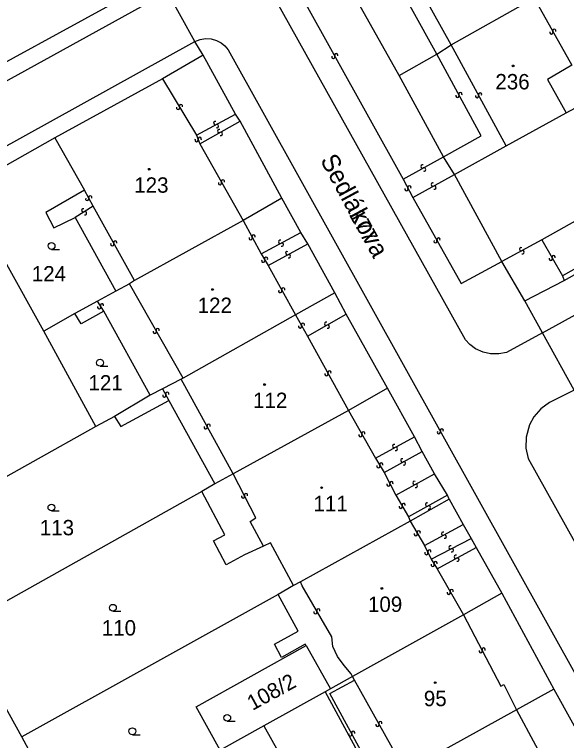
# Model space of a CAD drawing. Extents: x -600391 to -599491, y -1160176 to -1159402.
# Drawn here: x -600288.8 to -600227.7, y -1159912.4 to -1159832 of the extents above; entities that cross this region are included whole.
import ezdxf

# ---------------------------------------------------------------- set-up
doc = ezdxf.new("R2010")
doc.units = 0
for name, color, linetype in [('Level 1', 7, 'Continuous'), ('Level 11', 7, 'Continuous'), ('Level 13', 7, 'Continuous'), ('Level 3', 7, 'Continuous'), ('Level 4', 7, 'Continuous'), ('Level 5', 7, 'Continuous')]:
    doc.layers.add(name, color=color, linetype=linetype)

msp = doc.modelspace()

# ---------------------------------------------------------------- linework, layer by layer
at = {"layer": 'Level 1'}
for points in [[(-600246.18, -1159838.78), (-600254.51, -1159823.88)], [(-600272.73, -1159827.94), (-600300.01, -1159842.88)], [(-600268.81, -1159835), (-600271.82, -1159829.5)], [(-600240.43, -1159835.36), (-600231.24, -1159830.17)], [(-600267.88, -1159836.52), (-600268.81, -1159835)], [(-600242.02, -1159836.39), (-600240.43, -1159835.36)], [(-600267.88, -1159836.52), (-600272.39, -1159839.13)], [(-600264.3, -1159843.04), (-600267.88, -1159836.52)], [(-600246.18, -1159838.78), (-600242.02, -1159836.39)], [(-600227.68, -1159842.88), (-600223.47, -1159840.63), (-600223.45, -1159840.03), (-600223.3, -1159839.51), (-600223.07, -1159839.09), (-600222.75, -1159838.72), (-600222.28, -1159838.38), (-600221.8, -1159838.18), (-600221.24, -1159838.09), (-600220.7, -1159838.14), (-600220.19, -1159838.3), (-600219.88, -1159838.48), (-600215.56, -1159836.16)], [(-600241.28, -1159847.75), (-600246.18, -1159838.78)], [(-600272.39, -1159839.13), (-600284.31, -1159845.68)], [(-600234.32, -1159846.54), (-600227.68, -1159842.88)], [(-600263.79, -1159843.81), (-600264.3, -1159843.04)], [(-600259.17, -1159852.34), (-600263.79, -1159843.81)], [(-600284.31, -1159845.68), (-600294.32, -1159851.32)], [(-600284.31, -1159845.68), (-600281.03, -1159851.47)], [(-600240.07, -1159849.73), (-600234.32, -1159846.54)], [(-600240.07, -1159849.73), (-600241.28, -1159847.75)], [(-600234.8, -1159859.37), (-600240.07, -1159849.73)], [(-600227.9, -1159861.47), (-600208.01, -1159850.29)], [(-600285.53, -1159867.08), (-600294.32, -1159851.32)], [(-600281.03, -1159851.47), (-600285.31, -1159853.92), (-600284.4, -1159855.61), (-600282.05, -1159854.47)], [(-600259.17, -1159852.34), (-600263.45, -1159854.82)], [(-600257.06, -1159856.13), (-600259.17, -1159852.34)], [(-600282.05, -1159854.47), (-600277.54, -1159862.64)], [(-600263.45, -1159854.82), (-600275.49, -1159861.45)], [(-600256.28, -1159857.41), (-600257.06, -1159856.13)], [(-600253.31, -1159862.81), (-600256.28, -1159857.41)], [(-600232.25, -1159863.72), (-600234.8, -1159859.37)], [(-600275.49, -1159861.45), (-600276.04, -1159861.83)], [(-600232.25, -1159863.72), (-600227.9, -1159861.47)], [(-600276.04, -1159861.83), (-600277.54, -1159862.64)], [(-600277.54, -1159862.64), (-600279.58, -1159863.74)], [(-600253.31, -1159862.81), (-600257.67, -1159865.27)], [(-600252.05, -1159865.19), (-600253.31, -1159862.81)], [(-600279.58, -1159863.74), (-600282.08, -1159865.09)], [(-600230.31, -1159867.23), (-600232.25, -1159863.72)], [(-600282.08, -1159865.09), (-600285.53, -1159867.08)], [(-600278.88, -1159864.85), (-600281.38, -1159866.25), (-600282.08, -1159865.09)], [(-600273.74, -1159874.15), (-600278.88, -1159864.85)], [(-600257.67, -1159865.27), (-600270.1, -1159872.26)], [(-600247.47, -1159873.37), (-600252.05, -1159865.19)], [(-600279.76, -1159877.63), (-600285.53, -1159867.08)], [(-600226.79, -1159873.6), (-600230.31, -1159867.23)], [(-600270.32, -1159872.39), (-600272.38, -1159873.45)], [(-600270.1, -1159872.26), (-600270.32, -1159872.39)], [(-600272.38, -1159873.45), (-600273.74, -1159874.15)], [(-600247.47, -1159873.37), (-600251.8, -1159875.84)], [(-600244.49, -1159878.77), (-600247.47, -1159873.37)], [(-600273.74, -1159874.15), (-600277.69, -1159876.51)], [(-600277.69, -1159876.51), (-600276.98, -1159877.6), (-600271.67, -1159874.72)], [(-600271.67, -1159874.72), (-600266.6, -1159883.96)], [(-600251.8, -1159875.84), (-600264.54, -1159882.86)], [(-600277.69, -1159876.51), (-600279.76, -1159877.63)], [(-600279.76, -1159877.63), (-600300.73, -1159889.34)], [(-600243.65, -1159880.38), (-600244.49, -1159878.77)], [(-600242.27, -1159882.85), (-600243.65, -1159880.38)], [(-600264.54, -1159882.86), (-600266.6, -1159883.96)], [(-600240.84, -1159885.23), (-600242.27, -1159882.85)], [(-600266.6, -1159883.96), (-600268.03, -1159884.8)], [(-600268.03, -1159884.8), (-600294.72, -1159899.77)], [(-600261.19, -1159890.85), (-600263.31, -1159891.81), (-600265.35, -1159892.93), (-600266.73, -1159890.28), (-600265.49, -1159889.6), (-600268.03, -1159884.8)], [(-600240.66, -1159885.66), (-600240.84, -1159885.23)], [(-600240.66, -1159885.66), (-600244.97, -1159888.08)], [(-600240.66, -1159885.66), (-600239.08, -1159888.47)], [(-600244.97, -1159888.08), (-600257.12, -1159894.82)], [(-600239.08, -1159888.47), (-600238.21, -1159890.03)], [(-600238.21, -1159890.03), (-600237.66, -1159891.01)], [(-600257.87, -1159895.23), (-600260.44, -1159890.48), (-600261.19, -1159890.85)], [(-600237.66, -1159891.01), (-600234.81, -1159896.08)], [(-600257.12, -1159894.82), (-600257.87, -1159895.23)], [(-600257.87, -1159895.23), (-600259.59, -1159896.22)], [(-600259.59, -1159896.22), (-600287.96, -1159911.98)], [(-600256.49, -1159901.87), (-600256.58, -1159901.71), (-600259.19, -1159903.19), (-600259.97, -1159901.72), (-600257.35, -1159900.26), (-600259.59, -1159896.22)], [(-600234.81, -1159896.08), (-600239.07, -1159898.45)], [(-600234.81, -1159896.08), (-600229.06, -1159906.7)], [(-600239.07, -1159898.45), (-600251.33, -1159905.28)], [(-600287.96, -1159911.98), (-600293.45, -1159902.08)], [(-600265.99, -1159913.45), (-600268.66, -1159908.65), (-600256.49, -1159901.87)], [(-600256.49, -1159901.87), (-600253.78, -1159906.65)], [(-600251.33, -1159905.28), (-600253.78, -1159906.65)], [(-600254.37, -1159906.98), (-600261.15, -1159910.76)], [(-600253.78, -1159906.65), (-600254.37, -1159906.98)], [(-600254.37, -1159906.98), (-600249.34, -1159916.24)], [(-600229.06, -1159906.7), (-600233.2, -1159908.96)], [(-600229.06, -1159906.7), (-600224.75, -1159914.47)], [(-600233.2, -1159908.96), (-600244.6, -1159915.29)], [(-600261.15, -1159910.76), (-600265.99, -1159913.45)], [(-600261.15, -1159910.76), (-600255.53, -1159920.84)], [(-600285.41, -1159916.7), (-600287.96, -1159911.98)]]:
    msp.add_lwpolyline(points, dxfattribs=at)
at = {"layer": 'Level 13'}
for centre, start, end in [((-600229.321, -1159833.989), 156.39539, 28.98539), ((-600228.998, -1159833.811), 336.60985, 208.70785), ((-600253.148, -1159836.512), 336.3917, 208.4897), ((-600253.471, -1159836.689), 156.17724, 28.76724), ((-600239.723, -1159841.006), 155.8544, 27.9524), ((-600239.398, -1159840.833), 335.63994, 208.22994), ((-600237.543, -1159841.037), 156.02985, 28.12785), ((-600237.218, -1159840.862), 335.81539, 208.40539), ((-600270.342, -1159842.156), 338.68684, 210.78483), ((-600270.658, -1159842.345), 158.47238, 31.06238), ((-600266.536, -1159844.037), 65.72114, 297.81914), ((-600266.363, -1159844.362), 245.50669, 118.09669), ((-600266.109, -1159844.908), 66.78523, 298.88323), ((-600265.93, -1159845.231), 246.57077, 119.16077), ((-600268.604, -1159845.91), 146.47463, 19.06463), ((-600268.255, -1159845.791), 326.68909, 198.78708), ((-600243.599, -1159848.838), 66.64503, 298.74302), ((-600243.421, -1159849.161), 246.43057, 119.02057), ((-600266.021, -1159850.67), 156.69195, 29.28195), ((-600265.699, -1159850.491), 336.90641, 209.00441), ((-600245.046, -1159851.165), 335.40082, 207.49881), ((-600242.457, -1159850.838), 66.18353, 298.28153), ((-600242.282, -1159851.162), 245.96907, 118.55907), ((-600245.373, -1159851.336), 155.18636, 27.77636), ((-600280.713, -1159852.427), 156.12065, 28.21864), ((-600280.388, -1159852.252), 335.90619, 208.49619), ((-600281.158, -1159853.684), 69.42303, 302.01303), ((-600280.963, -1159853.997), 249.63749, 121.73549), ((-600262.297, -1159856.584), 335.52553, 207.62353), ((-600277.942, -1159857.428), 156.4687, 28.56669), ((-600277.619, -1159857.251), 336.25424, 208.84424), ((-600262.623, -1159856.756), 155.31108, 27.90108), ((-600259.346, -1159857.167), 65.82822, 297.92621), ((-600259.173, -1159857.492), 245.61376, 118.20376), ((-600242.151, -1159857.11), 156.51318, 29.10318), ((-600241.828, -1159856.931), 336.72763, 208.82563), ((-600258.566, -1159858.437), 65.78209, 297.88009), ((-600232.688, -1159857.998), 65.81423, 298.40423), ((-600232.513, -1159858.323), 246.02869, 118.12668), ((-600260.912, -1159859.064), 339.2563, 211.35429), ((-600258.393, -1159858.762), 245.56764, 118.15764), ((-600229.4, -1159859.051), 157.11919, 29.70919), ((-600229.079, -1159858.869), 337.33365, 209.43165), ((-600261.227, -1159859.257), 159.04184, 31.63184), ((-600259.018, -1159862.443), 336.15141, 208.24941), ((-600259.342, -1159862.618), 155.93695, 28.52695), ((-600279.387, -1159864.397), 159.60952, 31.70752), ((-600279.074, -1159864.203), 339.39506, 211.98506), ((-600256.83, -1159866.349), 337.4317, 209.5297), ((-600254.27, -1159866.239), 67.07414, 299.17214), ((-600273.231, -1159867.13), 157.03472, 29.13272), ((-600272.91, -1159866.95), 336.82027, 209.41027), ((-600257.15, -1159866.531), 157.21725, 29.80725), ((-600254.09, -1159866.56), 246.85969, 119.44969), ((-600254.222, -1159871.818), 155.91017, 28.50017), ((-600253.897, -1159871.643), 336.12463, 208.22263), ((-600272.181, -1159874.169), 156.36588, 28.95588), ((-600271.858, -1159873.991), 336.58033, 208.67833), ((-600267.268, -1159877.532), 336.05933, 208.64933), ((-600267.592, -1159877.708), 156.27378, 28.37178), ((-600250.139, -1159878.39), 337.05915, 209.15715), ((-600241.781, -1159878.229), 156.24801, 28.83801), ((-600241.458, -1159878.052), 336.46246, 208.56046), ((-600250.46, -1159878.57), 156.84469, 29.43469), ((-600246.727, -1159879.777), 66.02985, 298.12785), ((-600246.552, -1159880.102), 245.81539, 118.40539), ((-600245.828, -1159881.378), 66.45055, 298.54855), ((-600245.651, -1159881.701), 246.2361, 118.8261), ((-600248.468, -1159882.014), 158.01593, 30.60593), ((-600248.151, -1159881.827), 338.23039, 210.32838), ((-600247.364, -1159884.044), 154.5457, 27.1357), ((-600247.035, -1159883.877), 334.76016, 206.85815), ((-600244.497, -1159883.858), 66.1424, 298.2404), ((-600244.322, -1159884.182), 245.92794, 118.51794), ((-600263.465, -1159885.372), 154.45522, 26.55322), ((-600263.136, -1159885.207), 334.24076, 206.83076), ((-600245.68, -1159886.308), 337.80697, 209.90497), ((-600243.078, -1159886.258), 66.0202, 298.6102), ((-600245.999, -1159886.493), 157.59251, 30.18251), ((-600242.902, -1159886.582), 246.23465, 118.33265), ((-600244.329, -1159889.533), 157.62382, 30.21382), ((-600244.01, -1159889.348), 337.83828, 209.93628), ((-600241.307, -1159889.477), 65.88016, 297.97816), ((-600241.133, -1159889.802), 245.66571, 118.25571), ((-600240.512, -1159890.995), 64.4015, 296.4995), ((-600240.347, -1159891.324), 244.18704, 116.77704), ((-600243.166, -1159891.62), 153.26003, 25.85003), ((-600242.834, -1159891.46), 333.47449, 205.57248), ((-600239.907, -1159892.037), 66.12239, 298.22039), ((-600242.151, -1159892.746), 338.56783, 210.66583), ((-600239.732, -1159892.362), 245.90794, 118.49794), ((-600242.468, -1159892.935), 158.35337, 30.94338), ((-600240.68, -1159896.011), 157.01257, 29.60257), ((-600240.359, -1159895.83), 337.22703, 209.32503), ((-600255.44, -1159898.172), 157.68629, 29.78429), ((-600255.121, -1159897.988), 337.47183, 210.06183), ((-600237.153, -1159902.485), 154.92878, 27.51878), ((-600236.826, -1159902.316), 335.14323, 207.24123), ((-600248.259, -1159910.451), 336.4035, 208.9935), ((-600248.582, -1159910.629), 156.61796, 28.71595), ((-600251.593, -1159911.697), 155.96511, 28.06311), ((-600251.268, -1159911.523), 335.75065, 208.34065)]:
    msp.add_arc(centre, 0.184, start, end, dxfattribs=at)
at = {"layer": 'Level 3'}
for points in [[(-600230.31, -1159867.23), (-600234.28, -1159869.41), (-600235.16, -1159869.58), (-600236.07, -1159869.58), (-600236.89, -1159869.39), (-600237.73, -1159869.01), (-600238.36, -1159868.54), (-600238.85, -1159868.03), (-600259.85, -1159830.4), (-600267.23, -1159824.89), (-600328.56, -1159715.49), (-600329.16, -1159714.44), (-600329.45, -1159713.11), (-600329.33, -1159711.96), (-600329.03, -1159711.13)], [(-600240.43, -1159835.36), (-600248.6, -1159820.64)], [(-600242.02, -1159836.39), (-600250.24, -1159821.55)], [(-600260.89, -1159822.94), (-600245.74, -1159850.25)], [(-600373.95, -1159885.79), (-600271.82, -1159829.5)], [(-600230.31, -1159867.23), (-600164.72, -1159831.16), (-600163.95, -1159830.52), (-600163.4, -1159829.75)], [(-600231.24, -1159830.17), (-600227.07, -1159837.62), (-600229.77, -1159839.19), (-600227.68, -1159842.88)], [(-600268.81, -1159835), (-600268.21, -1159834.77), (-600267.62, -1159834.68), (-600267.01, -1159834.71), (-600266.39, -1159834.88), (-600265.88, -1159835.15), (-600265.47, -1159835.49), (-600265.11, -1159835.91), (-600218.12, -1159920.37), (-600217.94, -1159920.94), (-600217.91, -1159921.6), (-600218.02, -1159922.19), (-600218.24, -1159922.81), (-600218.57, -1159923.26), (-600218.96, -1159923.67), (-600219.39, -1159923.97)], [(-600369.85, -1159890.97), (-600268.81, -1159835)], [(-600234.32, -1159846.54), (-600240.43, -1159835.36)], [(-600241.28, -1159847.75), (-600237.11, -1159845.44), (-600242.02, -1159836.39)], [(-600272.39, -1159839.13), (-600268.6, -1159845.36)], [(-600268.6, -1159845.36), (-600264.3, -1159843.04)], [(-600268.26, -1159846.33), (-600263.79, -1159843.81)], [(-600268.6, -1159845.36), (-600268.26, -1159846.33)], [(-600210.89, -1159846.04), (-600230.39, -1159856.96)], [(-600210.89, -1159846.04), (-600208.7, -1159850.11), (-600228.09, -1159860.95)], [(-600268.26, -1159846.33), (-600263.45, -1159854.82)], [(-600245.74, -1159850.25), (-600241.28, -1159847.75)], [(-600244.67, -1159852.26), (-600240.07, -1159849.73)], [(-600245.74, -1159850.25), (-600244.67, -1159852.26)], [(-600280.07, -1159853.22), (-600281.03, -1159851.47)], [(-600244.67, -1159852.26), (-600239.31, -1159861.79), (-600234.8, -1159859.37)], [(-600280.07, -1159853.22), (-600282.05, -1159854.47)], [(-600275.49, -1159861.45), (-600280.07, -1159853.22)], [(-600263.45, -1159854.82), (-600261.47, -1159858.52)], [(-600261.47, -1159858.52), (-600257.06, -1159856.13)], [(-600260.68, -1159859.79), (-600256.28, -1159857.41)], [(-600230.39, -1159856.96), (-600234.8, -1159859.37)], [(-600230.39, -1159856.96), (-600228.09, -1159860.95)], [(-600261.47, -1159858.52), (-600260.68, -1159859.79)], [(-600260.68, -1159859.79), (-600257.67, -1159865.27)], [(-600228.09, -1159860.95), (-600227.9, -1159861.47)], [(-600270.1, -1159872.26), (-600276.04, -1159861.83)], [(-600278.88, -1159864.85), (-600279.58, -1159863.74)], [(-600257.67, -1159865.27), (-600256.31, -1159867.62)], [(-600256.31, -1159867.62), (-600252.05, -1159865.19)], [(-600256.31, -1159867.62), (-600251.8, -1159875.84)], [(-600264.54, -1159882.86), (-600270.32, -1159872.39)], [(-600272.38, -1159873.45), (-600271.67, -1159874.72)], [(-600226.79, -1159873.6), (-600229.16, -1159874.79), (-600229.52, -1159874.97), (-600230.51, -1159875.67), (-600231.28, -1159876.56), (-600231.76, -1159877.43), (-600232.13, -1159878.78), (-600232.17, -1159880), (-600231.89, -1159881.14), (-600211.75, -1159917.28), (-600210.89, -1159926.36), (-600152.6, -1160029.31), (-600151.79, -1160029.76)], [(-600251.8, -1159875.84), (-600248.79, -1159881.12)], [(-600248.79, -1159881.12), (-600244.49, -1159878.77)], [(-600247.84, -1159882.71), (-600243.65, -1159880.38)], [(-600248.79, -1159881.12), (-600247.84, -1159882.71)], [(-600261.19, -1159890.85), (-600262.68, -1159888.14), (-600262.06, -1159887.71), (-600264.54, -1159882.86)], [(-600247.84, -1159882.71), (-600246.55, -1159885.2)], [(-600246.55, -1159885.2), (-600242.27, -1159882.85)], [(-600246.55, -1159885.2), (-600245.14, -1159887.6)], [(-600240.84, -1159885.23), (-600245.14, -1159887.6)], [(-600245.14, -1159887.6), (-600244.97, -1159888.08)], [(-600244.97, -1159888.08), (-600243.37, -1159890.8)], [(-600243.37, -1159890.8), (-600239.08, -1159888.47)], [(-600242.64, -1159892.29), (-600238.21, -1159890.03)], [(-600243.37, -1159890.8), (-600242.64, -1159892.29)], [(-600241.98, -1159893.38), (-600237.66, -1159891.01)], [(-600242.64, -1159892.29), (-600241.98, -1159893.38)], [(-600241.98, -1159893.38), (-600239.07, -1159898.45)], [(-600251.33, -1159905.28), (-600251.48, -1159905.01), (-600252.25, -1159904.06), (-600252.99, -1159903.07), (-600253.52, -1159901.95), (-600253.64, -1159900.88), (-600256.92, -1159895.27), (-600257.12, -1159894.82)], [(-600239.07, -1159898.45), (-600234.91, -1159906.35), (-600234.58, -1159906.16), (-600233.2, -1159908.96)], [(-600251.13, -1159905.7), (-600251.33, -1159905.28)], [(-600249.01, -1159916.05), (-600253.85, -1159907.17), (-600251.13, -1159905.7)], [(-600245.71, -1159915.38), (-600251.13, -1159905.7)], [(-600233.2, -1159908.96), (-600228.97, -1159916.8)]]:
    msp.add_lwpolyline(points, dxfattribs=at)
at = {"layer": 'Level 5'}
for p, q in [((-600284.66, -1159858.01), (-600283.785, -1159858.01)), ((-600279.3, -1159870.93), (-600278.425, -1159870.93)), ((-600284.68, -1159886.96), (-600283.805, -1159886.96)), ((-600277.87, -1159898.05), (-600276.995, -1159898.05)), ((-600265.21, -1159910.24), (-600264.335, -1159910.24)), ((-600275.72, -1159911.73), (-600274.845, -1159911.73))]:
    msp.add_line(p, q, dxfattribs=at)
for centre, radius in [((-600233.56, -1159837.7), 0.09), ((-600233.56, -1159837.7), 0.0521), ((-600273.85, -1159849.14), 0.09), ((-600273.85, -1159849.14), 0.0521), ((-600284.66, -1159857.635), 0.375), ((-600266.84, -1159862.45), 0.09), ((-600266.84, -1159862.45), 0.0521), ((-600279.3, -1159870.555), 0.375), ((-600261.08, -1159872.97), 0.09), ((-600261.08, -1159872.97), 0.0521), ((-600254.76, -1159884.39), 0.09), ((-600254.76, -1159884.39), 0.0521), ((-600284.68, -1159886.585), 0.375), ((-600248.09, -1159895.54), 0.09), ((-600248.09, -1159895.54), 0.0521), ((-600277.87, -1159897.675), 0.375), ((-600242.19, -1159905.97), 0.09), ((-600242.19, -1159905.97), 0.0521), ((-600265.21, -1159909.865), 0.375), ((-600275.72, -1159911.355), 0.375)]:
    msp.add_circle(centre, radius, dxfattribs=at)

# ---------------------------------------------------------------- texts
at = {"layer": 'Level 11'}
msp.add_text('Sedlákova', height=2, rotation=298.46046, dxfattribs=at).set_placement((-600254.956, -1159848.131))
at = {"layer": 'Level 4'}
for s, p in [('236', (-600235.526, -1159840.3)), ('123', (-600275.509, -1159851.74)), ('124', (-600286.852, -1159861.56)), ('122', (-600268.487, -1159865.05)), ('121', (-600280.575, -1159873.63)), ('112', (-600262.355, -1159875.57)), ('111', (-600255.663, -1159886.99)), ('113', (-600285.967, -1159889.66)), ('109', (-600249.631, -1159898.14)), ('110', (-600279.104, -1159900.75)), ('95', (-600243.447, -1159908.57))]:
    msp.add_text(s, height=1.7, dxfattribs=at).set_placement(p)
for s, rotation, p in [('177', 298.8, (-600251.779, -1159854.14)), ('108/2', 28.8, (-600262.414, -1159909.105))]:
    msp.add_text(s, height=1.7, rotation=rotation, dxfattribs=at).set_placement(p)

doc.saveas('drawing.dxf')
